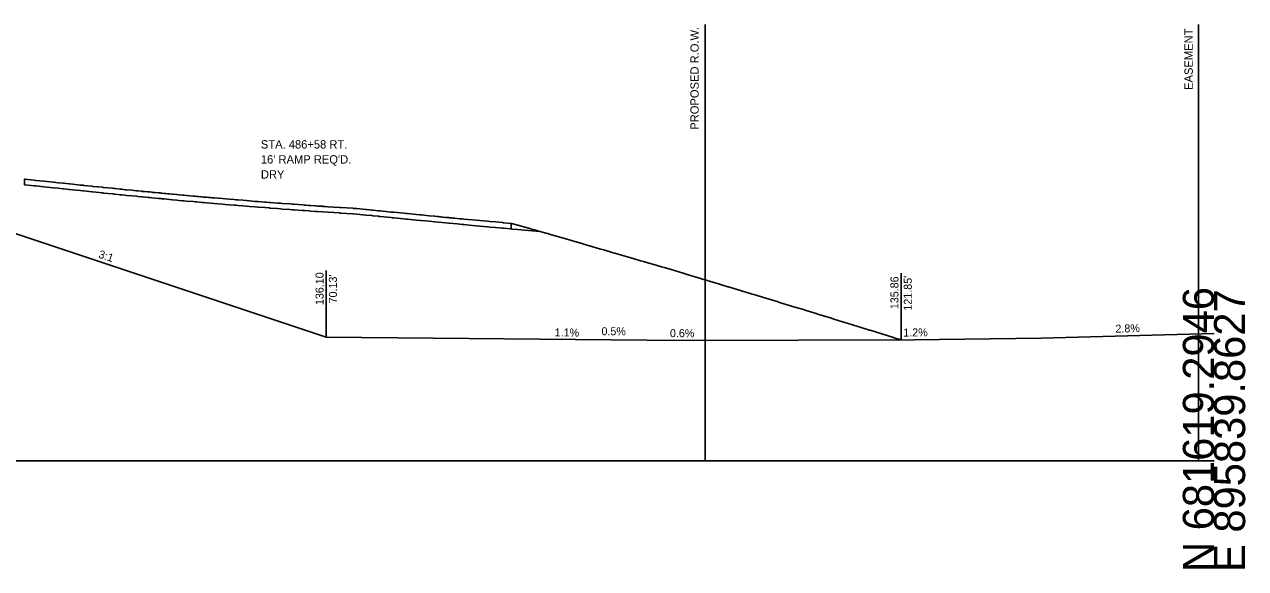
# Model space of a CAD drawing. Extents: x -26 to 4403, y -13 to 9578.
# Drawn here: x 3293 to 3402.8, y 8490.3 to 8539.2 of the extents above; entities that cross this region are included whole.
import ezdxf

# ---------------------------------------------------------------- set-up
doc = ezdxf.new("R2010")
doc.units = 0
for name, color, linetype in [('CONST_LV3', 7, 'Continuous'), ('DTM_CONTOURS_MINOR', 7, 'Continuous'), ('DTM_P_FINISHED_GRADE', 7, 'Continuous'), ('DTM_X_GROUND', 7, 'Continuous'), ('ROW_LINES', 7, 'Continuous'), ('X_PROFILES_1', 7, 'Continuous'), ('XS_CELL', 7, 'Continuous'), ('XS_P_DR_GRAVEL', 7, 'Continuous'), ('XS_P_DRAINAGE', 7, 'Continuous'), ('XS_P_GROUND', 7, 'Continuous'), ('XS_P_TX_CLEARZONE', 7, 'Continuous'), ('XS_P_TX_FS_BS', 7, 'Continuous')]:
    doc.layers.add(name, color=color, linetype=linetype)

msp = doc.modelspace()

# ---------------------------------------------------------------- linework, layer by layer
at = {"layer": 'CONST_LV3'}
msp.add_lwpolyline([(3292.96, 8525.32), (3293, 8525.31), (3293, 8525.31), (3293.86, 8525.22), (3294, 8525.2), (3294, 8525.2), (3294.73, 8525.13), (3295, 8525.1), (3295, 8525.1), (3295.59, 8525.03), (3296, 8524.99), (3296, 8524.99), (3296.46, 8524.94), (3296.46, 8524.94), (3296.5, 8524.94), (3297, 8524.89), (3297.02, 8524.88), (3297.34, 8524.85), (3297.99, 8524.78), (3298.02, 8524.78), (3298.27, 8524.76), (3298.31, 8524.75), (3299.03, 8524.68), (3299.09, 8524.67), (3299.13, 8524.66), (3300.03, 8524.58), (3300.04, 8524.56), (3300.07, 8524.56), (3300.88, 8524.49), (3300.91, 8524.49), (3301.05, 8524.46), (3301.13, 8524.46), (3301.59, 8524.41), (3301.74, 8524.4), (3302.05, 8524.36), (3302.16, 8524.35), (3302.64, 8524.31), (3303.06, 8524.27), (3303.18, 8524.25), (3303.54, 8524.22), (3304.06, 8524.17), (3304.22, 8524.16), (3304.44, 8524.13), (3304.52, 8524.12), (3305.16, 8524.07), (3305.25, 8524.06), (3305.35, 8524.05), (3306.06, 8523.98), (3306.27, 8523.96), (3306.28, 8523.95), (3306.68, 8523.92), (3306.91, 8523.9), (3307.2, 8523.87), (3307.31, 8523.86), (3307.57, 8523.84), (3308.19, 8523.79), (3308.34, 8523.77), (3308.64, 8523.74), (3309.08, 8523.7), (3309.37, 8523.68), (3309.54, 8523.66), (3309.86, 8523.63), (3310.04, 8523.62), (3310.4, 8523.59), (3310.79, 8523.56), (3311.05, 8523.54), (3311.43, 8523.5), (3311.86, 8523.47), (3312.02, 8523.46), (3312.17, 8523.44), (3312.64, 8523.41), (3312.94, 8523.38), (3312.97, 8523.38), (3313.45, 8523.33), (3313.97, 8523.3), (3314.01, 8523.29), (3314.29, 8523.27), (3314.69, 8523.24), (3314.99, 8523.22), (3315.08, 8523.21), (3315.73, 8523.16), (3316.02, 8523.14), (3316.16, 8523.12), (3316.86, 8523.08), (3317.06, 8523.06), (3317.23, 8523.05), (3318, 8522.99), (3318.14, 8522.98), (3318.16, 8522.98), (3318.3, 8522.97), (3319.14, 8522.91), (3319.2, 8522.91), (3319.65, 8522.88), (3319.81, 8522.87), (3320.28, 8522.83), (3320.31, 8522.83), (3321.33, 8522.77), (3321.42, 8522.76), (3321.42, 8522.76), (3322.53, 8522.69), (3322.55, 8522.69), (3322.56, 8522.68), (3322.87, 8522.67), (3323.69, 8522.58), (3323.71, 8522.58), (3323.76, 8522.58), (3324.83, 8522.47), (3324.88, 8522.46), (3324.99, 8522.45), (3325.5, 8522.4), (3325.97, 8522.35), (3326.1, 8522.34), (3326.22, 8522.33), (3327.11, 8522.24), (3327.33, 8522.22), (3327.45, 8522.21), (3328.24, 8522.13), (3328.59, 8522.09), (3328.68, 8522.09), (3329.38, 8522.02), (3329.88, 8521.97), (3329.91, 8521.97), (3330.56, 8521.9), (3331.15, 8521.85), (3331.2, 8521.84), (3331.46, 8521.82), (3332.16, 8521.75), (3332.38, 8521.73), (3332.5, 8521.72), (3333.28, 8521.65), (3333.61, 8521.62), (3333.94, 8521.59), (3334.64, 8521.52), (3334.84, 8521.5), (3335.36, 8521.46), (3336, 8521.4), (3336.08, 8521.39), (3336.76, 8521.33)], dxfattribs=at)
at = {"layer": 'DTM_P_FINISHED_GRADE'}
msp.add_lwpolyline([(3292.96, 8525.32), (3293, 8525.31), (3293, 8525.31), (3293.86, 8525.22), (3294, 8525.2), (3294, 8525.2), (3294.73, 8525.13), (3295, 8525.1), (3295, 8525.1), (3295.59, 8525.03), (3295.59, 8525.03), (3296, 8524.99), (3296.01, 8524.99), (3296.46, 8524.94), (3296.5, 8524.94), (3297, 8524.89), (3297.02, 8524.88), (3297.34, 8524.85), (3297.99, 8524.78), (3298.02, 8524.78), (3298.27, 8524.76), (3298.31, 8524.75), (3299.03, 8524.68), (3299.09, 8524.67), (3299.11, 8524.66), (3300, 8524.58), (3300.03, 8524.58), (3300.04, 8524.56), (3300.1, 8524.56), (3300.91, 8524.49), (3301.05, 8524.46), (3301.13, 8524.46), (3301.59, 8524.41), (3301.74, 8524.4), (3302.05, 8524.36), (3302.16, 8524.35), (3302.64, 8524.31), (3303.06, 8524.27), (3303.18, 8524.25), (3303.54, 8524.22), (3303.6, 8524.21), (3304.14, 8524.16), (3304.22, 8524.16), (3304.44, 8524.13), (3305.07, 8524.07), (3305.25, 8524.06), (3305.35, 8524.05), (3305.55, 8524.03), (3306.27, 8523.96), (3306.28, 8523.95), (3306.68, 8523.92), (3306.91, 8523.9), (3307.2, 8523.87), (3307.31, 8523.86), (3307.57, 8523.84), (3308.19, 8523.79), (3308.34, 8523.77), (3308.49, 8523.76), (3308.93, 8523.72), (3309.08, 8523.7), (3309.37, 8523.68), (3309.71, 8523.65), (3310.04, 8523.62), (3310.4, 8523.59), (3310.79, 8523.56), (3311.05, 8523.54), (3311.43, 8523.5), (3311.86, 8523.47), (3312.02, 8523.46), (3312.17, 8523.44), (3312.64, 8523.41), (3312.94, 8523.38), (3312.97, 8523.38), (3313.22, 8523.36), (3313.7, 8523.31), (3313.97, 8523.3), (3314.01, 8523.29), (3314.59, 8523.25), (3314.99, 8523.22), (3315.08, 8523.21), (3315.73, 8523.16), (3316.02, 8523.14), (3316.16, 8523.12), (3316.86, 8523.08), (3317.06, 8523.06), (3317.23, 8523.05), (3318, 8522.99), (3318.14, 8522.98), (3318.16, 8522.98), (3318.57, 8522.95), (3318.71, 8522.94), (3319.14, 8522.91), (3319.2, 8522.91), (3319.37, 8522.89), (3320.28, 8522.83), (3320.31, 8522.83), (3321.33, 8522.77), (3321.42, 8522.76), (3321.42, 8522.76), (3322.53, 8522.69), (3322.55, 8522.69), (3322.56, 8522.68), (3322.87, 8522.67), (3323.69, 8522.58), (3323.71, 8522.58), (3324.23, 8522.53), (3324.32, 8522.52), (3324.83, 8522.47), (3324.88, 8522.46), (3324.99, 8522.45), (3325.97, 8522.35), (3326.1, 8522.34), (3326.22, 8522.33), (3327.11, 8522.24), (3327.33, 8522.22), (3327.45, 8522.21), (3328.24, 8522.13), (3328.59, 8522.09), (3328.68, 8522.09), (3329.38, 8522.02), (3329.88, 8521.97), (3329.91, 8521.97), (3330.22, 8521.94), (3330.87, 8521.87), (3331.15, 8521.85), (3331.2, 8521.84), (3331.92, 8521.78), (3332.38, 8521.73), (3332.5, 8521.72), (3333.28, 8521.65), (3333.61, 8521.62), (3333.94, 8521.59), (3334.64, 8521.52), (3334.84, 8521.5), (3335.36, 8521.46), (3336, 8521.4), (3336.08, 8521.39), (3336.76, 8521.33)], dxfattribs=at)
at = {"layer": 'DTM_X_GROUND'}
for p, q in [((3384.44, 8511.01), (3392.22, 8511.23)), ((3392.22, 8511.23), (3400, 8511.44)), ((3320.13, 8511.1), (3352.17, 8510.8)), ((3320.13, 8511.1), (3352.17, 8510.8)), ((3352.17, 8510.8), (3373.03, 8510.87)), ((3373.03, 8510.87), (3384.44, 8511.01))]:
    msp.add_line(p, q, dxfattribs=at)
at = {"layer": 'ROW_LINES'}
for p, q in [((3354.23, 8500), (3354.23, 8539.21)), ((3398.59, 8500), (3398.59, 8539.21))]:
    msp.add_line(p, q, dxfattribs=at)
at = {"layer": 'XS_CELL'}
msp.add_line((3250, 8500), (3400, 8500), dxfattribs=at)
at = {"layer": 'XS_P_DR_GRAVEL'}
for points in [[(3292.98, 8525.31), (3292.98, 8524.81), (3293, 8524.81), (3293, 8524.81), (3293.86, 8524.72), (3294, 8524.7), (3294, 8524.7), (3294.73, 8524.63), (3295, 8524.6), (3295, 8524.6), (3295.59, 8524.53), (3295.59, 8524.53), (3296, 8524.49), (3296.01, 8524.49), (3296.46, 8524.44), (3296.5, 8524.44), (3297, 8524.39), (3297.02, 8524.38), (3297.34, 8524.35), (3297.99, 8524.28), (3298.02, 8524.28), (3298.27, 8524.26), (3298.31, 8524.25), (3299.03, 8524.18), (3299.09, 8524.17), (3299.11, 8524.16), (3300, 8524.08), (3300.03, 8524.08), (3300.04, 8524.06), (3300.1, 8524.06), (3300.91, 8523.99), (3301.05, 8523.96), (3301.13, 8523.96), (3301.59, 8523.91), (3301.74, 8523.9), (3302.05, 8523.86), (3302.16, 8523.85), (3302.64, 8523.81), (3303.06, 8523.77), (3303.18, 8523.75), (3303.54, 8523.72), (3303.6, 8523.71), (3304.14, 8523.66), (3304.22, 8523.66), (3304.44, 8523.63), (3305.07, 8523.57), (3305.25, 8523.56), (3305.35, 8523.55), (3305.55, 8523.53), (3306.27, 8523.46), (3306.28, 8523.45), (3306.68, 8523.42), (3306.91, 8523.4), (3307.2, 8523.37), (3307.31, 8523.36), (3307.57, 8523.34), (3308.19, 8523.29), (3308.34, 8523.27), (3308.49, 8523.26), (3308.93, 8523.22), (3309.08, 8523.2), (3309.37, 8523.18), (3309.71, 8523.15), (3310.04, 8523.12), (3310.4, 8523.09), (3310.79, 8523.06), (3311.05, 8523.04), (3311.43, 8523), (3311.86, 8522.97), (3312.02, 8522.96), (3312.17, 8522.94), (3312.64, 8522.91), (3312.94, 8522.88), (3312.97, 8522.88), (3313.22, 8522.86), (3313.7, 8522.81), (3313.97, 8522.8), (3314.01, 8522.79), (3314.59, 8522.75), (3314.99, 8522.72), (3315.08, 8522.71), (3315.73, 8522.66), (3316.02, 8522.64), (3316.16, 8522.62), (3316.86, 8522.58), (3317.06, 8522.56), (3317.23, 8522.55), (3318, 8522.49), (3318.14, 8522.48), (3318.16, 8522.48), (3318.57, 8522.45), (3318.71, 8522.44), (3319.14, 8522.41), (3319.2, 8522.41), (3319.37, 8522.39), (3320.28, 8522.33), (3320.31, 8522.33), (3321.33, 8522.27), (3321.42, 8522.26), (3321.42, 8522.26), (3322.53, 8522.19), (3322.55, 8522.19), (3322.56, 8522.18), (3322.87, 8522.17), (3323.69, 8522.08), (3323.71, 8522.08), (3324.23, 8522.03), (3324.32, 8522.02), (3324.83, 8521.97), (3324.88, 8521.96), (3324.99, 8521.95), (3325.97, 8521.85), (3326.1, 8521.84), (3326.22, 8521.83), (3327.11, 8521.74), (3327.33, 8521.72), (3327.45, 8521.71), (3328.24, 8521.63), (3328.59, 8521.59), (3328.68, 8521.59), (3329.38, 8521.52), (3329.88, 8521.47), (3329.91, 8521.47), (3330.22, 8521.44), (3330.87, 8521.37), (3331.15, 8521.35), (3331.2, 8521.34), (3331.92, 8521.28), (3332.38, 8521.23), (3332.5, 8521.22), (3333.28, 8521.15), (3333.61, 8521.12), (3333.94, 8521.09), (3334.64, 8521.02), (3334.84, 8521), (3335.36, 8520.96), (3336, 8520.9), (3336.08, 8520.89), (3336.76, 8520.83), (3336.76, 8521.33), (3336.08, 8521.39), (3336, 8521.4), (3335.36, 8521.46), (3334.84, 8521.5), (3334.64, 8521.52), (3333.94, 8521.59), (3333.61, 8521.62), (3333.28, 8521.65), (3332.5, 8521.72), (3332.38, 8521.73), (3331.92, 8521.78), (3331.2, 8521.84), (3331.15, 8521.85), (3330.87, 8521.87), (3330.22, 8521.94), (3329.91, 8521.97), (3329.88, 8521.97), (3329.38, 8522.02), (3328.68, 8522.09), (3328.59, 8522.09), (3328.24, 8522.13), (3327.45, 8522.21), (3327.33, 8522.22), (3327.11, 8522.24), (3326.22, 8522.33), (3326.1, 8522.34), (3325.97, 8522.35), (3324.99, 8522.45), (3324.88, 8522.46), (3324.83, 8522.47), (3324.32, 8522.52), (3324.23, 8522.53), (3323.71, 8522.58), (3323.69, 8522.58), (3322.87, 8522.67), (3322.56, 8522.68), (3322.55, 8522.69), (3322.53, 8522.69), (3321.42, 8522.76), (3321.42, 8522.76), (3321.33, 8522.77), (3320.31, 8522.83), (3320.28, 8522.83), (3319.37, 8522.89), (3319.2, 8522.91), (3319.14, 8522.91), (3318.71, 8522.94), (3318.57, 8522.95), (3318.16, 8522.98), (3318.14, 8522.98), (3318, 8522.99), (3317.23, 8523.05), (3317.06, 8523.06), (3316.86, 8523.08), (3316.16, 8523.12), (3316.02, 8523.14), (3315.73, 8523.16), (3315.08, 8523.21), (3314.99, 8523.22), (3314.59, 8523.25), (3314.01, 8523.29), (3313.97, 8523.3), (3313.7, 8523.31), (3313.22, 8523.36), (3312.97, 8523.38), (3312.94, 8523.38), (3312.64, 8523.41), (3312.17, 8523.44), (3312.02, 8523.46), (3311.86, 8523.47), (3311.43, 8523.5), (3311.05, 8523.54), (3310.79, 8523.56), (3310.4, 8523.59), (3310.04, 8523.62), (3309.71, 8523.65), (3309.37, 8523.68), (3309.08, 8523.7), (3308.93, 8523.72), (3308.49, 8523.76), (3308.34, 8523.77), (3308.19, 8523.79), (3307.57, 8523.84), (3307.31, 8523.86), (3307.2, 8523.87), (3306.91, 8523.9), (3306.68, 8523.92), (3306.28, 8523.95), (3306.27, 8523.96), (3305.55, 8524.03), (3305.35, 8524.05), (3305.25, 8524.06), (3305.07, 8524.07), (3304.44, 8524.13), (3304.22, 8524.16), (3304.14, 8524.16), (3303.6, 8524.21), (3303.54, 8524.22), (3303.18, 8524.25), (3303.06, 8524.27), (3302.64, 8524.31), (3302.16, 8524.35), (3302.05, 8524.36), (3301.74, 8524.4), (3301.59, 8524.41), (3301.13, 8524.46), (3301.05, 8524.46), (3300.91, 8524.49), (3300.1, 8524.56), (3300.04, 8524.56), (3300.03, 8524.58), (3300, 8524.58), (3299.11, 8524.66), (3299.09, 8524.67), (3299.03, 8524.68), (3298.31, 8524.75), (3298.27, 8524.76), (3298.02, 8524.78), (3297.99, 8524.78), (3297.34, 8524.85), (3297.02, 8524.88), (3297, 8524.89), (3296.5, 8524.94), (3296.46, 8524.94), (3296.01, 8524.99), (3296, 8524.99), (3295.59, 8525.03), (3295.59, 8525.03), (3295, 8525.1), (3295, 8525.1), (3294.73, 8525.13), (3294, 8525.2), (3294, 8525.2), (3293.86, 8525.22), (3293, 8525.31), (3293, 8525.31), (3292.98, 8525.31)], [(3336.76, 8520.83), (3336.83, 8520.82), (3337.34, 8520.78), (3338.33, 8520.69), (3338.68, 8520.66), (3339.36, 8520.6)]]:
    msp.add_lwpolyline(points, dxfattribs=at)
at = {"layer": 'XS_P_GROUND'}
for points in [[(3320.13, 8511.1), (3280.78, 8524.21), (3280, 8524.47), (3279.77, 8524.53), (3268, 8527.47)], [(3336.76, 8521.33), (3336.83, 8521.31), (3336.83, 8521.31), (3337.34, 8521.17), (3337.36, 8521.16), (3338.33, 8520.89), (3338.35, 8520.89), (3338.68, 8520.79), (3338.75, 8520.78), (3339.88, 8520.45), (3339.9, 8520.45), (3340.06, 8520.41), (3340.2, 8520.37), (3341.47, 8520), (3341.48, 8520), (3341.48, 8520), (3341.69, 8519.94), (3342.92, 8519.58), (3342.94, 8519.57), (3343.03, 8519.55), (3343.3, 8519.47), (3344.41, 8519.15), (3344.51, 8519.12), (3344.83, 8519.03), (3345.11, 8518.95), (3345.95, 8518.7), (3346.1, 8518.66), (3346.48, 8518.54), (3346.8, 8518.46), (3347.53, 8518.24), (3347.82, 8518.16), (3348.41, 8517.98), (3348.68, 8517.91), (3349.16, 8517.76), (3349.59, 8517.64), (3350.29, 8517.43), (3350.52, 8517.36), (3350.85, 8517.27), (3351.46, 8517.09), (3352.25, 8516.85), (3352.41, 8516.8), (3352.59, 8516.75), (3353.42, 8516.5), (3354.28, 8516.24), (3354.34, 8516.22), (3354.39, 8516.21), (3355.41, 8515.9), (3356.26, 8515.64), (3356.32, 8515.62), (3356.4, 8515.6), (3357.48, 8515.28), (3358.19, 8515.05), (3358.45, 8514.98), (3358.6, 8514.93), (3359.67, 8514.61), (3360.2, 8514.45), (3360.69, 8514.3), (3360.9, 8514.23), (3361.91, 8513.93), (3362.28, 8513.81), (3363.06, 8513.58), (3363.3, 8513.5), (3364.21, 8513.22), (3364.45, 8513.15), (3365.58, 8512.8), (3365.81, 8512.73), (3366.58, 8512.49), (3366.7, 8512.45), (3368.27, 8511.97), (3368.44, 8511.92), (3369.01, 8511.74), (3369.06, 8511.73), (3371.16, 8511.07), (3371.2, 8511.06), (3371.51, 8510.97), (3371.51, 8510.97), (3371.85, 8510.86)]]:
    msp.add_lwpolyline(points, dxfattribs=at)
at = {"layer": 'XS_P_TX_CLEARZONE'}
for p, q in [((3320.13, 8511.1), (3320.13, 8517.1)), ((3320.13, 8511.1), (3320.13, 8517.1)), ((3371.85, 8510.86), (3371.85, 8516.86))]:
    msp.add_line(p, q, dxfattribs=at)

# ---------------------------------------------------------------- texts
at = {"layer": 'DTM_CONTOURS_MINOR'}
msp.add_text('X', height=0.12, dxfattribs=at).set_placement((3320.09, 8511.04))
at = {"layer": 'ROW_LINES'}
for s, p in [('PROPOSED R.O.W.', (3353.64, 8529.75)), ('EASEMENT ', (3398.09, 8533.33))]:
    msp.add_text(s, height=0.75, rotation=90, dxfattribs=at).set_placement(p)
at = {"layer": 'X_PROFILES_1'}
for p in [(3320.09, 8511.04), (3371.81, 8510.8)]:
    msp.add_text('X', height=0.12, dxfattribs=at).set_placement(p)
at = {"layer": 'XS_CELL'}
for s, p in [('N 681619.2946', (3400, 8490)), ('E 895839.8627', (3402.8, 8490))]:
    msp.add_text(s, height=2.8, rotation=90, dxfattribs=at).set_placement(p)
at = {"layer": 'XS_P_DRAINAGE'}
for s, p in [('STA. 486+58 RT.', (3314.25, 8528.06)), ("16' RAMP REQ'D.", (3314.25, 8526.71)), ('DRY', (3314.25, 8525.36))]:
    msp.add_text(s, height=0.75, dxfattribs=at).set_placement(p)
at = {"layer": 'XS_P_TX_CLEARZONE'}
for s, p in [('136.10', (3319.89, 8513.99)), ('136.10', (3319.89, 8513.99)), ("70.13'", (3321.09, 8514.14)), ("70.13'", (3321.09, 8514.14)), ('135.86', (3371.61, 8513.62)), ("121.85'", (3372.81, 8513.49))]:
    msp.add_text(s, height=0.72, rotation=90, dxfattribs=at).set_placement(p)
at = {"layer": 'XS_P_TX_FS_BS'}
for s, rotation, p in [('3:1', 341.5668, (3299.58, 8518.27)), ('1.1%', 359.3939, (3340.68, 8511.18)), ('1.1%', 359.3939, (3340.68, 8511.18)), ('0.5%', 359.7339, (3344.89, 8511.28)), ('0.6%', 359.6329, (3351.05, 8511.11)), ('0.6%', 359.6329, (3351.05, 8511.11)), ('1.2%', 0.672, (3372.05, 8511.16)), ('1.2%', 0.672, (3372.05, 8511.16)), ('2.8%', 1.6106, (3391.14, 8511.5)), ('2.8%', 1.6106, (3391.14, 8511.5))]:
    msp.add_text(s, height=0.72, rotation=rotation, dxfattribs=at).set_placement(p)

doc.saveas('drawing.dxf')
